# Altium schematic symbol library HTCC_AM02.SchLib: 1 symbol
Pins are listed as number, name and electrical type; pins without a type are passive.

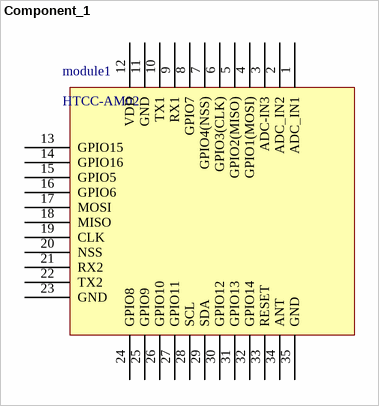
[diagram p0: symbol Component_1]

## Component_1
designator module1, comment HTCC-AM02
footprint HTCC-AM02
pins: 1 ADC_IN1, 2 ADC_IN2, 3 ADC-IN3, 4 GPIO1(MOSI), 5 GPIO2(MISO), 6 GPIO3(CLK), 7 GPIO4(NSS), 8 GPIO7, 9 RX1, 10 TX1, 11 GND, 12 VDD, 13 GPIO15, 14 GPIO16, 15 GPIO5, 16 GPIO6, 17 MOSI, 18 MISO, 19 CLK, 20 NSS, 21 RX2, 22 TX2, 23 GND, 24 GPIO8, 25 GPIO9, 26 GPIO10, 27 GPIO11, 28 SCL, 29 SDA, 30 GPIO12, 31 GPIO13, 32 GPIO14, 33 RESET, 34 ANT, 35 GND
